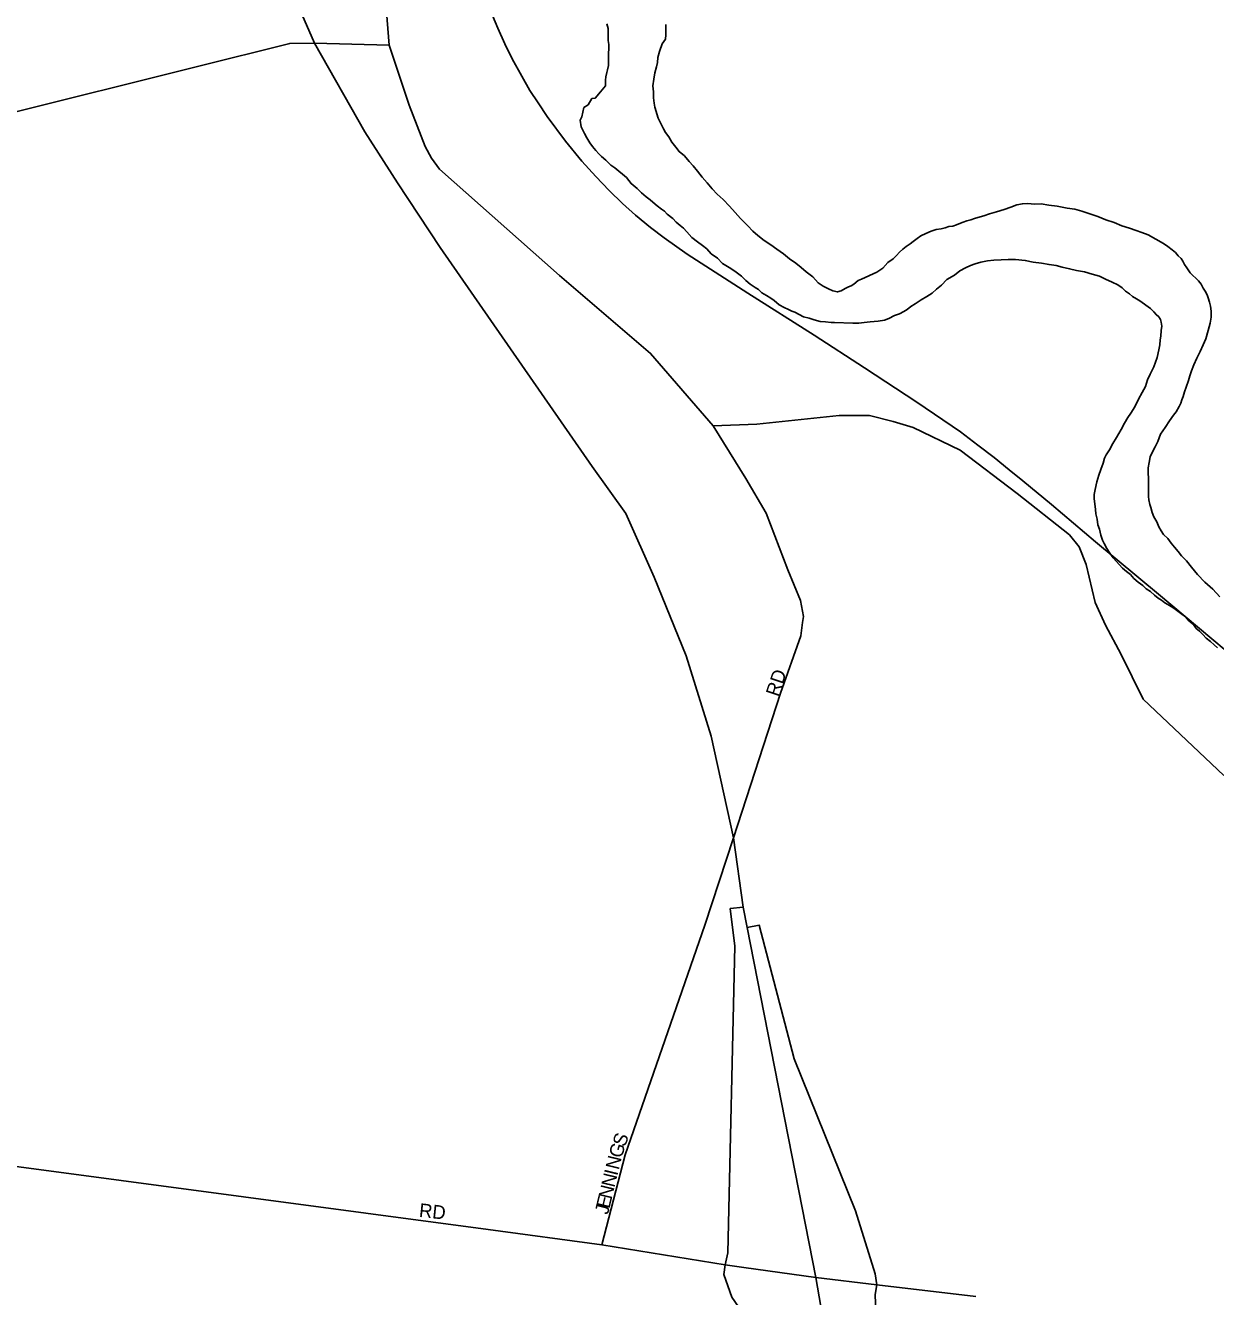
# Model space of a CAD drawing. Extents: x -561 to 1170, y 0 to 846.
# Drawn here: x 243.42 to 255.12, y 224.52 to 237.01 of the extents above; entities that cross this region are included whole.
import ezdxf

# ---------------------------------------------------------------- set-up
doc = ezdxf.new("R2010")
doc.units = 0
for name, color, linetype in [('GM_X_City_Street', 7, 'Continuous'), ('GM_X_City_Street_Text', 7, 'Continuous'), ('GM_X_Interchange_Ramps', 7, 'Continuous'), ('GM_X_Major_River', 7, 'Continuous'), ('GM_X_Rail_Line', 7, 'Continuous'), ('GM_X_State_Route', 7, 'Continuous')]:
    doc.layers.add(name, color=color, linetype=linetype)

msp = doc.modelspace()

# ---------------------------------------------------------------- linework, layer by layer
at = {"layer": 'GM_X_City_Street'}
for points in [[(246.993, 236.811), (246.993, 236.811), (246.901, 237.96), (246.846, 239.617), (246.848, 240.883), (246.815, 241.182), (246.808, 241.341), (246.834, 241.494), (246.87, 241.644), (246.887, 241.849), (246.903, 242.031), (246.904, 243.339)], [(245.095, 236.599), (246.016, 236.83), (246.259, 236.833), (246.993, 236.811)], [(250.178, 233.072), (249.562, 233.784), (248.667, 234.551), (247.487, 235.594), (247.41, 235.703), (247.348, 235.818), (247.188, 236.223), (246.993, 236.811)], [(238.485, 228.437), (240.179, 229.206), (240.798, 229.55), (241, 229.797), (241.219, 230.264), (241.715, 231.622), (242.335, 233.198), (242.359, 233.538), (242.391, 234.727), (242.393, 235.213), (242.456, 235.467), (242.691, 235.835), (242.804, 235.999), (242.979, 236.093), (243.205, 236.127), (245.095, 236.599)], [(255.197, 229.638), (254.404, 230.386), (254.188, 230.826), (254.035, 231.113), (253.931, 231.337), (253.844, 231.711), (253.773, 231.885), (253.678, 232.001), (253.164, 232.407), (252.606, 232.833), (252.144, 233.056), (251.947, 233.114), (251.714, 233.173), (251.416, 233.173), (250.608, 233.088), (250.178, 233.072)], [(251.056, 231.141), (251.064, 231.2), (251.036, 231.357), (250.911, 231.658), (250.699, 232.216), (250.497, 232.556), (250.178, 233.072)], [(249.083, 225.026), (249.312, 225.909), (250.097, 228.168), (250.376, 229.025), (250.84, 230.446), (251.039, 231.008), (251.056, 231.141)], [(239.596, 226.295), (247.967, 225.176)], [(247.967, 225.176), (249.083, 225.026)], [(249.083, 225.026), (250.294, 224.83), (250.48, 224.804)], [(250.48, 224.804), (251.185, 224.705), (251.786, 224.634), (252.758, 224.518)]]:
    msp.add_lwpolyline(points, dxfattribs=at)
at = {"layer": 'GM_X_Interchange_Ramps'}
for points in [[(250.473, 228.345), (250.345, 228.329), (250.389, 227.959), (250.322, 224.948), (250.294, 224.83)], [(251.786, 224.634), (251.769, 224.741), (251.577, 225.359), (250.973, 226.854), (250.63, 228.166), (250.513, 228.144)], [(250.294, 224.83), (250.283, 224.735), (250.361, 224.511), (250.659, 224.079), (250.989, 223.597), (251.224, 223.185), (251.292, 222.858), (251.388, 222.194), (251.422, 221.564), (251.433, 221.037), (251.556, 221.038)], [(251.557, 221.163), (251.709, 221.159), (251.763, 222.398), (251.797, 223.361), (251.786, 224.096), (251.769, 224.539), (251.786, 224.634)]]:
    msp.add_lwpolyline(points, dxfattribs=at)
at = {"layer": 'GM_X_Major_River'}
for points in [[(249.132, 237.021), (249.144, 236.977), (249.144, 236.945), (249.145, 236.902), (249.145, 236.858), (249.151, 236.82), (249.152, 236.777), (249.147, 236.734), (249.148, 236.69), (249.149, 236.614), (249.138, 236.571), (249.133, 236.544), (249.123, 236.5), (249.118, 236.468), (249.119, 236.414), (249.071, 236.353), (249.018, 236.293), (248.985, 236.287), (248.948, 236.227), (248.905, 236.2), (248.885, 236.107), (248.869, 236.075), (248.881, 236.01), (248.898, 235.972), (248.914, 235.945), (248.936, 235.902), (248.964, 235.854), (248.992, 235.816), (249.025, 235.779), (249.052, 235.746), (249.08, 235.72), (249.124, 235.682), (249.173, 235.634), (249.211, 235.607), (249.326, 235.511), (249.37, 235.452), (249.43, 235.404), (249.474, 235.361), (249.518, 235.324), (249.557, 235.292), (249.584, 235.271), (249.628, 235.233), (249.671, 235.201), (249.699, 235.18), (249.726, 235.153), (249.781, 235.11), (249.814, 235.073), (249.852, 235.041), (249.885, 235.014), (249.918, 234.977), (249.968, 234.923), (250.022, 234.88), (250.072, 234.843), (250.115, 234.811), (250.159, 234.763), (250.219, 234.72), (250.269, 234.667), (250.351, 234.619), (250.405, 234.582), (250.455, 234.544), (250.498, 234.502), (250.542, 234.464), (250.591, 234.432), (250.624, 234.411), (250.657, 234.379), (250.701, 234.352), (250.744, 234.326), (250.777, 234.304)], [(250.777, 234.304), (250.744, 234.326), (250.701, 234.352), (250.657, 234.379), (250.624, 234.411), (250.591, 234.432), (250.542, 234.464), (250.498, 234.502), (250.455, 234.544), (250.405, 234.582), (250.351, 234.619), (250.269, 234.667), (250.219, 234.72), (250.159, 234.763), (250.115, 234.811), (250.072, 234.843), (250.022, 234.88), (249.968, 234.923), (249.918, 234.977), (249.885, 235.014), (249.852, 235.041), (249.814, 235.073), (249.781, 235.11), (249.726, 235.153), (249.699, 235.18), (249.671, 235.201), (249.628, 235.233), (249.584, 235.271), (249.557, 235.292), (249.518, 235.324), (249.474, 235.361), (249.43, 235.404), (249.37, 235.452), (249.326, 235.511), (249.211, 235.607), (249.173, 235.634), (249.124, 235.682), (249.08, 235.72), (249.052, 235.746), (249.025, 235.779), (248.992, 235.816), (248.964, 235.854), (248.936, 235.902), (248.914, 235.945), (248.898, 235.972), (248.881, 236.01), (248.869, 236.075), (248.885, 236.107), (248.905, 236.2), (248.948, 236.227), (248.985, 236.287), (249.018, 236.293), (249.071, 236.353), (249.119, 236.414), (249.118, 236.468), (249.123, 236.5), (249.133, 236.544), (249.138, 236.571), (249.149, 236.614), (249.148, 236.69), (249.147, 236.734), (249.152, 236.777), (249.151, 236.82), (249.145, 236.858), (249.145, 236.902), (249.144, 236.945), (249.144, 236.977), (249.132, 237.021)], [(249.743, 235.912), (249.71, 235.955), (249.688, 235.992), (249.671, 236.03), (249.654, 236.063), (249.637, 236.095), (249.604, 236.203), (249.598, 236.241), (249.591, 236.295), (249.591, 236.354), (249.584, 236.414), (249.594, 236.479), (249.604, 236.539), (249.62, 236.598), (249.63, 236.642), (249.635, 236.691), (249.65, 236.751), (249.676, 236.827), (249.708, 236.87), (249.713, 236.914), (249.712, 236.963), (249.711, 237.017)], [(249.711, 237.017), (249.712, 236.963), (249.713, 236.914), (249.708, 236.87), (249.676, 236.827), (249.65, 236.751), (249.635, 236.691), (249.63, 236.642), (249.62, 236.598), (249.604, 236.539), (249.594, 236.479), (249.584, 236.414), (249.591, 236.354), (249.591, 236.295), (249.598, 236.241), (249.604, 236.203), (249.637, 236.095), (249.654, 236.063), (249.671, 236.03), (249.688, 235.992), (249.71, 235.955), (249.743, 235.912)], [(254.893, 234.549), (254.865, 234.576), (254.832, 234.624), (254.81, 234.657), (254.794, 234.689), (254.777, 234.716), (254.749, 234.743), (254.722, 234.775), (254.689, 234.801), (254.645, 234.833), (254.602, 234.865), (254.454, 234.95), (254.389, 234.971), (254.335, 234.992), (254.269, 235.013), (254.193, 235.039), (254.117, 235.071), (254.036, 235.097), (253.959, 235.129), (253.878, 235.155), (253.802, 235.181), (253.731, 235.202), (253.655, 235.212), (253.557, 235.232), (253.476, 235.242), (253.4, 235.252), (253.335, 235.251), (253.27, 235.256), (253.216, 235.255), (253.162, 235.243), (253.103, 235.221), (253.038, 235.199), (252.963, 235.176), (252.893, 235.154), (252.839, 235.137), (252.779, 235.12), (252.747, 235.108), (252.709, 235.097), (252.672, 235.086), (252.634, 235.075), (252.607, 235.063), (252.569, 235.047), (252.532, 235.035), (252.494, 235.03), (252.456, 235.018), (252.418, 235.007), (252.37, 235.001), (252.321, 234.984), (252.267, 234.962), (252.219, 234.94), (252.182, 234.912), (252.144, 234.884), (252.112, 234.862), (252.074, 234.835), (252.042, 234.807), (252.01, 234.78), (251.978, 234.747), (251.946, 234.714), (251.893, 234.676), (251.845, 234.621), (251.786, 234.582), (251.635, 234.515), (251.603, 234.499), (251.56, 234.466), (251.533, 234.449), (251.506, 234.438), (251.474, 234.421), (251.436, 234.399), (251.399, 234.388), (251.355, 234.398), (251.311, 234.419), (251.257, 234.446), (251.208, 234.478), (251.158, 234.537), (251.093, 234.585), (251.043, 234.627), (250.989, 234.67), (250.929, 234.713), (250.868, 234.761), (250.803, 234.809), (250.743, 234.851), (250.677, 234.894), (250.617, 234.942), (250.568, 234.985), (250.518, 235.038), (250.447, 235.108), (250.392, 235.167), (250.337, 235.231), (250.276, 235.295), (250.216, 235.349), (250.167, 235.402), (250.117, 235.461), (250.068, 235.515), (250.024, 235.574), (249.98, 235.628), (249.941, 235.67), (249.897, 235.724), (249.842, 235.767), (249.809, 235.81), (249.771, 235.858), (249.743, 235.912)], [(249.743, 235.912), (249.771, 235.858), (249.809, 235.81), (249.842, 235.767), (249.897, 235.724), (249.941, 235.67), (249.98, 235.628), (250.024, 235.574), (250.068, 235.515), (250.117, 235.461), (250.167, 235.402), (250.216, 235.349), (250.276, 235.295), (250.337, 235.231), (250.392, 235.167), (250.447, 235.108), (250.518, 235.038), (250.568, 234.985), (250.617, 234.942), (250.677, 234.894), (250.743, 234.851), (250.803, 234.809), (250.868, 234.761), (250.929, 234.713), (250.989, 234.67), (251.043, 234.627), (251.093, 234.585), (251.158, 234.537), (251.208, 234.478), (251.257, 234.446), (251.311, 234.419), (251.355, 234.398), (251.399, 234.388), (251.436, 234.399), (251.474, 234.421), (251.506, 234.438), (251.533, 234.449), (251.56, 234.466), (251.603, 234.499), (251.635, 234.515), (251.786, 234.582), (251.845, 234.621), (251.893, 234.676), (251.946, 234.714), (251.978, 234.747), (252.01, 234.78), (252.042, 234.807), (252.074, 234.835), (252.112, 234.862), (252.144, 234.884), (252.182, 234.912), (252.219, 234.94), (252.267, 234.962), (252.321, 234.984), (252.37, 235.001), (252.418, 235.007), (252.456, 235.018), (252.494, 235.03), (252.532, 235.035), (252.569, 235.047), (252.607, 235.063), (252.634, 235.075), (252.672, 235.086), (252.709, 235.097), (252.747, 235.108), (252.779, 235.12), (252.839, 235.137), (252.893, 235.154), (252.963, 235.176), (253.038, 235.199), (253.103, 235.221), (253.162, 235.243), (253.216, 235.255), (253.27, 235.256), (253.335, 235.251), (253.4, 235.252), (253.476, 235.242), (253.557, 235.232), (253.655, 235.212), (253.731, 235.202), (253.802, 235.181), (253.878, 235.155), (253.959, 235.129), (254.036, 235.097), (254.117, 235.071), (254.193, 235.039), (254.269, 235.013), (254.335, 234.992), (254.389, 234.971), (254.454, 234.95), (254.602, 234.865), (254.645, 234.833), (254.689, 234.801), (254.722, 234.775), (254.749, 234.743), (254.777, 234.716), (254.794, 234.689), (254.81, 234.657), (254.832, 234.624), (254.865, 234.576), (254.893, 234.549)], [(250.777, 234.304), (250.826, 234.262), (250.876, 234.235), (250.919, 234.214), (250.952, 234.198), (250.979, 234.188), (251.023, 234.167), (251.066, 234.145), (251.121, 234.13), (251.17, 234.114), (251.229, 234.099), (251.283, 234.094), (251.338, 234.089), (251.37, 234.089), (251.549, 234.081), (251.608, 234.082), (251.662, 234.088), (251.722, 234.094), (251.798, 234.1), (251.862, 234.112), (251.905, 234.128), (251.959, 234.156), (252.008, 234.173), (252.051, 234.195), (252.083, 234.217), (252.12, 234.245), (252.163, 234.272), (252.222, 234.311), (252.276, 234.344), (252.33, 234.377), (252.372, 234.416), (252.421, 234.454), (252.474, 234.509), (252.549, 234.553), (252.603, 234.597), (252.656, 234.625), (252.705, 234.647), (252.753, 234.664), (252.807, 234.681), (252.872, 234.693), (252.937, 234.699), (253.007, 234.705), (253.077, 234.706), (253.148, 234.707), (253.245, 234.697), (253.321, 234.682), (253.403, 234.672), (253.479, 234.657), (253.549, 234.647), (253.609, 234.631), (253.68, 234.616), (253.75, 234.6), (253.826, 234.585), (253.902, 234.564), (253.973, 234.544), (254.033, 234.512), (254.098, 234.485), (254.153, 234.459), (254.196, 234.427), (254.229, 234.395), (254.268, 234.368), (254.3, 234.342), (254.339, 234.32), (254.371, 234.299), (254.475, 234.225), (254.508, 234.192), (254.53, 234.166), (254.557, 234.144), (254.574, 234.117), (254.58, 234.09), (254.586, 234.053), (254.581, 234.009), (254.576, 233.955), (254.571, 233.917), (254.567, 233.868), (254.557, 233.819), (254.541, 233.743), (254.51, 233.651), (254.473, 233.58), (254.447, 233.525), (254.426, 233.46), (254.395, 233.4), (254.358, 233.335), (254.321, 233.258), (254.284, 233.198), (254.252, 233.155), (254.22, 233.1), (254.188, 233.035), (254.141, 232.958), (254.104, 232.898), (254.072, 232.838), (254.04, 232.789), (254.025, 232.756), (254.009, 232.707), (253.988, 232.642), (253.967, 232.588), (253.947, 232.522), (253.931, 232.446), (253.921, 232.397), (253.922, 232.354), (253.928, 232.305)], [(253.928, 232.305), (253.922, 232.354), (253.921, 232.397), (253.931, 232.446), (253.947, 232.522), (253.967, 232.588), (253.988, 232.642), (254.009, 232.707), (254.025, 232.756), (254.04, 232.789), (254.072, 232.838), (254.104, 232.898), (254.141, 232.958), (254.188, 233.035), (254.22, 233.1), (254.252, 233.155), (254.284, 233.198), (254.321, 233.258), (254.358, 233.335), (254.395, 233.4), (254.426, 233.46), (254.447, 233.525), (254.473, 233.58), (254.51, 233.651), (254.541, 233.743), (254.557, 233.819), (254.567, 233.868), (254.571, 233.917), (254.576, 233.955), (254.581, 234.009), (254.586, 234.053), (254.58, 234.09), (254.574, 234.117), (254.557, 234.144), (254.53, 234.166), (254.508, 234.192), (254.475, 234.225), (254.371, 234.299), (254.339, 234.32), (254.3, 234.342), (254.268, 234.368), (254.229, 234.395), (254.196, 234.427), (254.153, 234.459), (254.098, 234.485), (254.033, 234.512), (253.973, 234.544), (253.902, 234.564), (253.826, 234.585), (253.75, 234.6), (253.68, 234.616), (253.609, 234.631), (253.549, 234.647), (253.479, 234.657), (253.403, 234.672), (253.321, 234.682), (253.245, 234.697), (253.148, 234.707), (253.077, 234.706), (253.007, 234.705), (252.937, 234.699), (252.872, 234.693), (252.807, 234.681), (252.753, 234.664), (252.705, 234.647), (252.656, 234.625), (252.603, 234.597), (252.549, 234.553), (252.474, 234.509), (252.421, 234.454), (252.372, 234.416), (252.33, 234.377), (252.276, 234.344), (252.222, 234.311), (252.163, 234.272), (252.12, 234.245), (252.083, 234.217), (252.051, 234.195), (252.008, 234.173), (251.959, 234.156), (251.905, 234.128), (251.862, 234.112), (251.798, 234.1), (251.722, 234.094), (251.662, 234.088), (251.608, 234.082), (251.549, 234.081), (251.37, 234.089), (251.338, 234.089), (251.283, 234.094), (251.229, 234.099), (251.17, 234.114), (251.121, 234.13), (251.066, 234.145), (251.023, 234.167), (250.979, 234.188), (250.952, 234.198), (250.919, 234.214), (250.876, 234.235), (250.826, 234.262), (250.777, 234.304)], [(255.158, 231.394), (255.087, 231.469), (255.01, 231.538), (254.939, 231.613), (254.878, 231.683), (254.829, 231.747), (254.779, 231.796), (254.746, 231.839), (254.713, 231.882), (254.68, 231.919), (254.647, 231.967), (254.603, 232.005), (254.581, 232.042), (254.559, 232.08), (254.537, 232.129), (254.509, 232.177), (254.492, 232.22), (254.48, 232.269), (254.469, 232.301), (254.458, 232.344), (254.457, 232.377), (254.457, 232.415), (254.456, 232.453), (254.456, 232.507), (254.453, 232.659), (254.464, 232.713), (254.474, 232.767), (254.495, 232.816), (254.521, 232.865), (254.547, 232.92), (254.573, 232.991), (254.621, 233.056), (254.664, 233.122), (254.701, 233.176), (254.727, 233.209), (254.759, 233.264), (254.775, 233.296), (254.785, 233.329), (254.796, 233.362), (254.811, 233.405), (254.827, 233.454), (254.848, 233.519), (254.863, 233.563), (254.879, 233.612), (254.9, 233.672), (254.931, 233.737), (254.963, 233.802), (254.994, 233.868), (255.021, 233.928), (255.041, 234.009), (255.062, 234.08), (255.072, 234.14), (255.071, 234.199), (255.065, 234.248), (255.054, 234.286), (255.042, 234.329), (255.031, 234.361), (255.014, 234.394), (254.992, 234.426), (254.975, 234.464), (254.948, 234.496), (254.92, 234.522), (254.893, 234.549)], [(254.893, 234.549), (254.92, 234.522), (254.948, 234.496), (254.975, 234.464), (254.992, 234.426), (255.014, 234.394), (255.031, 234.361), (255.042, 234.329), (255.054, 234.286), (255.065, 234.248), (255.071, 234.199), (255.072, 234.14), (255.062, 234.08), (255.041, 234.009), (255.021, 233.928), (254.994, 233.868), (254.963, 233.802), (254.931, 233.737), (254.9, 233.672), (254.879, 233.612), (254.863, 233.563), (254.848, 233.519), (254.827, 233.454), (254.811, 233.405), (254.796, 233.362), (254.785, 233.329), (254.775, 233.296), (254.759, 233.264), (254.727, 233.209), (254.701, 233.176), (254.664, 233.122), (254.621, 233.056), (254.573, 232.991), (254.547, 232.92), (254.521, 232.865), (254.495, 232.816), (254.474, 232.767), (254.464, 232.713), (254.453, 232.659), (254.456, 232.507), (254.456, 232.453), (254.457, 232.415), (254.457, 232.377), (254.458, 232.344), (254.469, 232.301), (254.48, 232.269), (254.492, 232.22), (254.509, 232.177), (254.537, 232.129), (254.559, 232.08), (254.581, 232.042), (254.603, 232.005), (254.647, 231.967), (254.68, 231.919), (254.713, 231.882), (254.746, 231.839), (254.779, 231.796), (254.829, 231.747), (254.878, 231.683), (254.939, 231.613), (255.01, 231.538), (255.087, 231.469), (255.158, 231.394)], [(253.928, 232.305), (253.934, 232.251), (253.94, 232.208), (253.952, 232.154), (253.958, 232.1), (253.975, 232.057), (253.986, 231.997), (254.003, 231.949), (254.02, 231.916), (254.048, 231.868), (254.075, 231.82), (254.108, 231.777), (254.202, 231.675), (254.24, 231.643), (254.278, 231.611), (254.311, 231.573), (254.355, 231.536), (254.399, 231.504), (254.432, 231.472), (254.476, 231.445), (254.514, 231.408), (254.552, 231.381), (254.585, 231.36), (254.618, 231.333), (254.662, 231.307), (254.705, 231.28), (254.743, 231.253), (254.782, 231.221), (254.82, 231.195), (254.853, 231.157), (254.897, 231.12), (254.924, 231.082), (254.957, 231.056), (254.99, 231.023), (255.023, 230.986), (255.067, 230.954), (255.1, 230.922), (255.133, 230.89)], [(255.133, 230.89), (255.1, 230.922), (255.067, 230.954), (255.023, 230.986), (254.99, 231.023), (254.957, 231.056), (254.924, 231.082), (254.897, 231.12), (254.853, 231.157), (254.82, 231.195), (254.782, 231.221), (254.743, 231.253), (254.705, 231.28), (254.662, 231.307), (254.618, 231.333), (254.585, 231.36), (254.552, 231.381), (254.514, 231.408), (254.476, 231.445), (254.432, 231.472), (254.399, 231.504), (254.355, 231.536), (254.311, 231.573), (254.278, 231.611), (254.24, 231.643), (254.202, 231.675), (254.108, 231.777), (254.075, 231.82), (254.048, 231.868), (254.02, 231.916), (254.003, 231.949), (253.986, 231.997), (253.975, 232.057), (253.958, 232.1), (253.952, 232.154), (253.94, 232.208), (253.934, 232.251), (253.928, 232.305)]]:
    msp.add_lwpolyline(points, dxfattribs=at)
at = {"layer": 'GM_X_Rail_Line'}
msp.add_lwpolyline([(255.742, 230.423), (254.553, 231.419), (253.935, 231.934), (253.504, 232.3), (253.222, 232.531), (253.087, 232.641), (252.939, 232.761), (252.779, 232.882), (252.607, 233.013), (252.179, 233.305), (251.664, 233.644), (251.169, 233.964), (250.518, 234.376), (249.922, 234.76), (249.697, 234.92), (249.561, 235.02), (249.413, 235.142), (249.287, 235.256), (249.156, 235.384), (249.023, 235.523), (248.887, 235.673), (248.725, 235.87), (248.546, 236.113), (248.458, 236.245), (248.377, 236.368), (248.296, 236.509), (248.203, 236.679), (248.129, 236.824), (248.06, 236.978), (247.967, 237.204)], dxfattribs=at)
at = {"layer": 'GM_X_State_Route'}
msp.add_lwpolyline([(251.521, 222.771), (251.185, 224.705), (250.513, 228.144), (250.473, 228.345), (250.376, 229.025), (250.157, 230.024), (249.911, 230.813), (249.598, 231.586), (249.318, 232.211), (248.989, 232.672), (247.493, 234.826), (247.076, 235.461), (246.753, 235.961), (246.259, 236.833), (245.848, 237.771), (245.64, 238.299), (245.437, 238.856), (245.322, 239.185), (245.274, 239.341), (245.085, 240.043), (244.945, 240.721), (244.827, 241.355), (244.738, 242.035), (244.621, 244.316)], dxfattribs=at)

# ---------------------------------------------------------------- texts
at = {"layer": 'GM_X_City_Street_Text'}
for s, rotation, p in [('RD', 71.5614, (250.819, 230.404)), ('S', 70.5024, (249.311, 225.982)), ('G', 72.7333, (249.276, 225.87)), ('N', 76.3878, (249.249, 225.757)), ('N', 76.4779, (249.207, 225.584)), ('I', 76.4515, (249.235, 225.699)), ('N', 76.4779, (249.179, 225.468)), ('RD', 353.9832, (247.282, 225.301)), ('J', 76.4515, (249.143, 225.318)), ('E', 76.4848, (249.157, 225.376))]:
    msp.add_text(s, height=0.135, rotation=rotation, dxfattribs=at).set_placement(p)

doc.saveas('drawing.dxf')
